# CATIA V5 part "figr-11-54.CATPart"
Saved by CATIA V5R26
Part number: Part1
Bounding box of the stored display mesh (mm): x -49.998 to 49.998, y -70 to 70, z 0 to 80.773
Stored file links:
  D:\_Deepak\CATIA\CATIA V5-6R2016_Deepak\Resources\Part files\Partfiles\c11_catia_v5_6r2016_prt\figr-11-54.CATPart
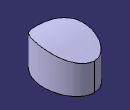
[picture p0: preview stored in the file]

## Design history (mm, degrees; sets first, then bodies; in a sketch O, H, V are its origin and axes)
Set1
  Extrude1: Element1 Sketch2, Lim1 82, Lim2 70, Direction yz-plane
Body1 (main body)
  Sketch1 on xy-plane, origin (0, 0, 0), H (1, 0, 0), V (0, 1, 0)
    ellipse A1 centre (0, 0) semi-axes 70, 50 rotation 90
    point P1 (50, 0)
    coincidence: P1 H, A1 P1
  Pad1: profile Sketch1, direction (0, 0, 1), length 84
  Split1: SplitPlane Extrude1
  Sketch2 on yz-plane, origin (0, 0, 0), H (0, 1, 0), V (0, 0, 1)
    spline S1 through (-90, 50) (-30, 80) (50, 70) (90, 60)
